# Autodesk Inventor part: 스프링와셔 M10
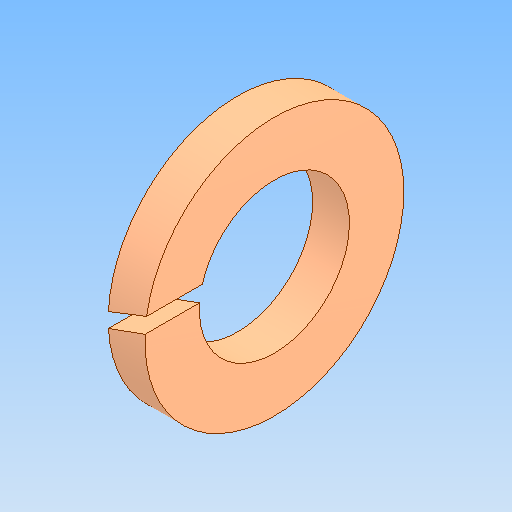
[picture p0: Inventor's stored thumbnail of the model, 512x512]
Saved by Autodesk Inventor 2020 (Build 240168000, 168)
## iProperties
Created: 2024-09
Part Number: 스프링와셔 M10
Material: 강철, 연강
Description: 스프링 잠금 와셔
Document SubType Name: Modeling
Designer: oem
Density: 7.85 g/cm^3
Appearance: 기본값
Author: jhkim
Sending System: Autodesk Inventor 2025
Preprocessor: ST-DEVELOPER v20
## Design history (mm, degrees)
feature "Solid1"
node "솔리드1"
